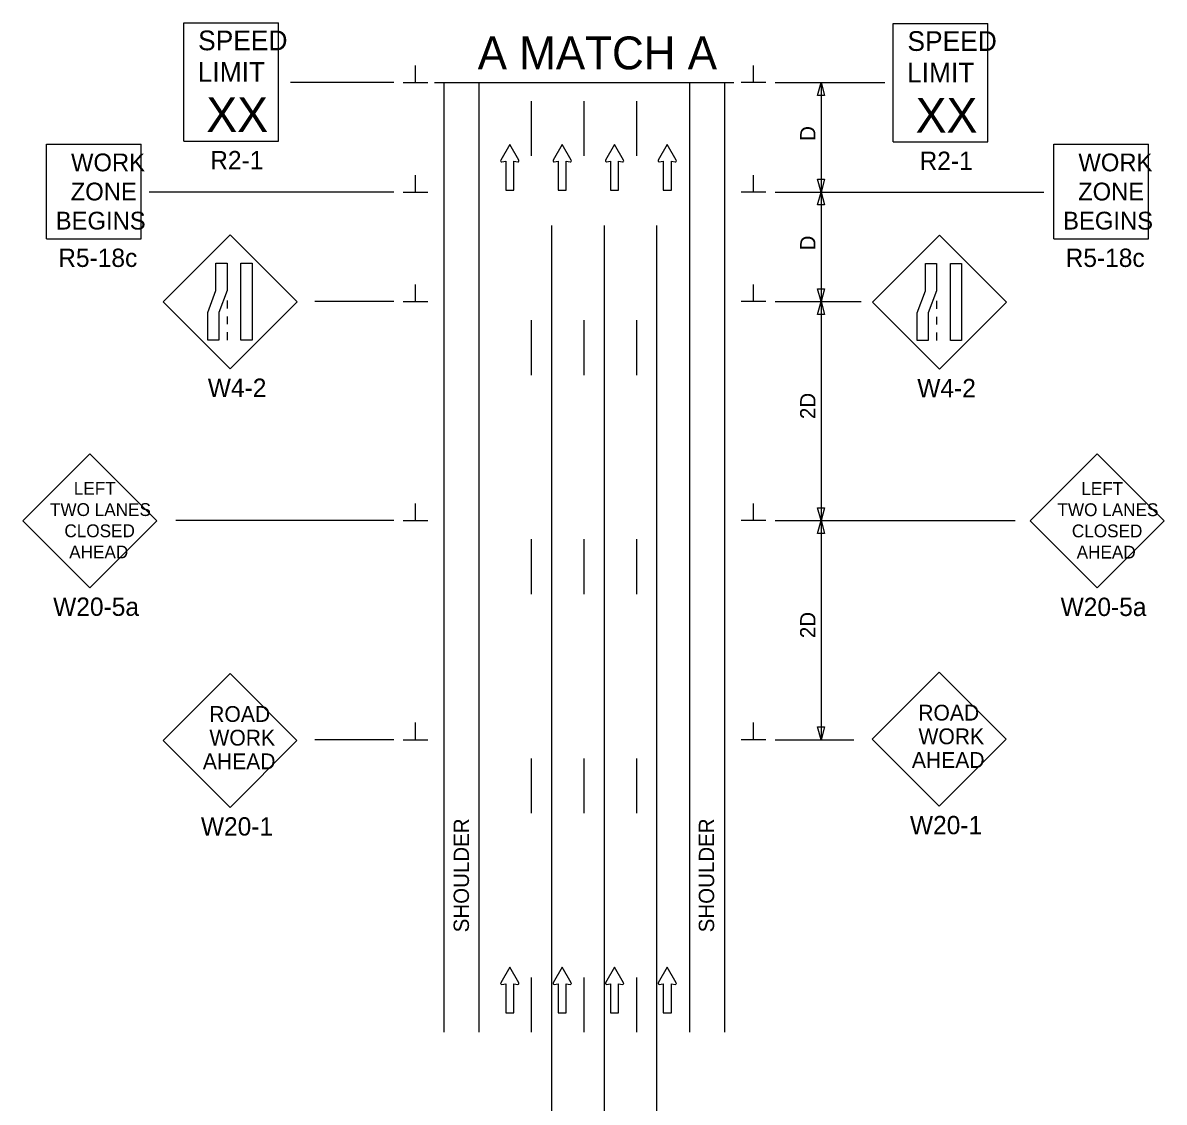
# Model space of a CAD drawing. Extents: x 16604 to 19504, y 6997 to 8305.
# Drawn here: x 17835 to 18356, y 7711 to 8204 of the extents above; entities that cross this region are included whole.
import ezdxf

# ---------------------------------------------------------------- set-up
doc = ezdxf.new("R2010")
doc.units = 0
for name, color, linetype in [('ALI_LEGAL_EX', 7, 'Continuous'), ('MT_SCRATCH_LEVEL_E', 7, 'Continuous'), ('PAVT_EDGE_EX', 7, 'Continuous'), ('TRAFFIC_SIGNS_PR', 7, 'Continuous'), ('TYPICAL_TEXT_DIMEN_PR', 7, 'Continuous')]:
    doc.layers.add(name, color=color, linetype=linetype)

msp = doc.modelspace()

# ---------------------------------------------------------------- linework, layer by layer
at = {"layer": 'ALI_LEGAL_EX'}
for p, q in [((18076.31, 7500.83), (18076.31, 8111.03)), ((18100.31, 7500.83), (18100.31, 8111.03)), ((18124.31, 7500.83), (18124.31, 8111.03))]:
    msp.add_line(p, q, dxfattribs=at)
for points in [[(18067.08, 8142.78), (18067.08, 8167.78)], [(18091.08, 8142.78), (18091.08, 8167.78)], [(18115.08, 8142.78), (18115.08, 8167.78)], [(18067.08, 8042.78), (18067.08, 8067.78)], [(18091.08, 8042.78), (18091.08, 8067.78)], [(18115.08, 8042.78), (18115.08, 8067.78)], [(18067.08, 7942.78), (18067.08, 7967.78)], [(18091.08, 7942.78), (18091.08, 7967.78)], [(18115.08, 7942.78), (18115.08, 7967.78)], [(18067.08, 7842.78), (18067.08, 7867.78)], [(18091.08, 7842.78), (18091.08, 7867.78)], [(18115.08, 7842.78), (18115.08, 7867.78)], [(18067.08, 7742.78), (18067.08, 7767.78)], [(18091.08, 7742.78), (18091.08, 7767.78)], [(18115.08, 7742.78), (18115.08, 7767.78)]]:
    msp.add_lwpolyline(points, dxfattribs=at)
at = {"layer": 'MT_SCRATCH_LEVEL_E'}
for p, q in [((18057.12, 8148.06), (18053.01, 8140.82)), ((18061.27, 8140.82), (18057.12, 8148.06)), ((18081.02, 8148.06), (18076.91, 8140.82)), ((18085.17, 8140.82), (18081.02, 8148.06)), ((18104.93, 8148.06), (18100.82, 8140.82)), ((18109.08, 8140.82), (18104.93, 8148.06)), ((18128.98, 8148.06), (18124.87, 8140.82)), ((18133.13, 8140.82), (18128.98, 8148.06)), ((18053.49, 8140.13), (18055.27, 8140.45)), ((18055.27, 8140.45), (18055.27, 8127.19)), ((18059.01, 8127.19), (18059.01, 8140.45)), ((18059.01, 8140.45), (18060.79, 8140.13)), ((18077.4, 8140.13), (18079.17, 8140.45)), ((18079.17, 8140.45), (18079.17, 8127.19)), ((18082.91, 8127.19), (18082.91, 8140.45)), ((18082.91, 8140.45), (18084.69, 8140.13)), ((18101.3, 8140.13), (18103.08, 8140.45)), ((18103.08, 8140.45), (18103.08, 8127.19)), ((18106.82, 8127.19), (18106.82, 8140.45)), ((18106.82, 8140.45), (18108.6, 8140.13)), ((18125.35, 8140.13), (18127.13, 8140.45)), ((18127.13, 8140.45), (18127.13, 8127.19)), ((18130.87, 8127.19), (18130.87, 8140.45)), ((18130.87, 8140.45), (18132.65, 8140.13)), ((18055.27, 8127.19), (18059.01, 8127.19)), ((18079.17, 8127.19), (18082.91, 8127.19)), ((18103.08, 8127.19), (18106.82, 8127.19)), ((18127.13, 8127.19), (18130.87, 8127.19)), ((18057.12, 7772.53), (18053.01, 7765.29)), ((18061.27, 7765.29), (18057.12, 7772.53)), ((18081.02, 7772.53), (18076.91, 7765.29)), ((18085.17, 7765.29), (18081.02, 7772.53)), ((18104.93, 7772.53), (18100.82, 7765.29)), ((18109.08, 7765.29), (18104.93, 7772.53)), ((18128.98, 7772.53), (18124.87, 7765.29)), ((18133.13, 7765.29), (18128.98, 7772.53)), ((18053.49, 7764.61), (18055.27, 7764.92)), ((18055.27, 7764.92), (18055.27, 7751.66)), ((18059.01, 7751.66), (18059.01, 7764.92)), ((18059.01, 7764.92), (18060.79, 7764.61)), ((18077.4, 7764.61), (18079.17, 7764.92)), ((18079.17, 7764.92), (18079.17, 7751.66)), ((18082.91, 7751.66), (18082.91, 7764.92)), ((18082.91, 7764.92), (18084.69, 7764.61)), ((18101.3, 7764.61), (18103.08, 7764.92)), ((18103.08, 7764.92), (18103.08, 7751.66)), ((18106.82, 7751.66), (18106.82, 7764.92)), ((18106.82, 7764.92), (18108.6, 7764.61)), ((18125.35, 7764.61), (18127.13, 7764.92)), ((18127.13, 7764.92), (18127.13, 7751.66)), ((18130.87, 7751.66), (18130.87, 7764.92)), ((18130.87, 7764.92), (18132.65, 7764.61)), ((18055.27, 7751.66), (18059.01, 7751.66)), ((18079.17, 7751.66), (18082.91, 7751.66)), ((18103.08, 7751.66), (18106.82, 7751.66)), ((18127.13, 7751.66), (18130.87, 7751.66))]:
    msp.add_line(p, q, dxfattribs=at)
for centre, start, end in [((18053.42, 8140.59), 150.4248, 279.9638), ((18060.86, 8140.59), 260.0362, 29.7731), ((18077.32, 8140.59), 150.4248, 279.9638), ((18084.76, 8140.59), 260.0362, 29.7731), ((18101.22, 8140.59), 150.4248, 279.9638), ((18108.67, 8140.59), 260.0362, 29.7731), ((18125.28, 8140.59), 150.4248, 279.9638), ((18132.72, 8140.59), 260.0362, 29.7731), ((18053.42, 7765.06), 150.4248, 279.9638), ((18060.86, 7765.07), 260.0362, 29.7731), ((18077.32, 7765.06), 150.4248, 279.9638), ((18084.76, 7765.07), 260.0362, 29.7731), ((18101.22, 7765.06), 150.4248, 279.9638), ((18108.67, 7765.07), 260.0362, 29.7731), ((18125.28, 7765.06), 150.4248, 279.9638), ((18132.72, 7765.07), 260.0362, 29.7731)]:
    msp.add_arc(centre, 0.463, start, end, dxfattribs=at)
at = {"layer": 'PAVT_EDGE_EX'}
for p, q in [((18027.08, 8176.3), (18027.08, 7742.78)), ((18043.08, 8176.3), (18043.08, 7742.78)), ((18139.08, 8176.3), (18139.08, 7742.78)), ((18155.08, 8176.3), (18155.08, 7742.78))]:
    msp.add_line(p, q, dxfattribs=at)
at = {"layer": 'TRAFFIC_SIGNS_PR'}
for p, q in [((17908.41, 8203.55), (17951.61, 8203.55)), ((17908.41, 8149.55), (17908.41, 8203.55)), ((17951.61, 8149.55), (17951.61, 8203.55)), ((18232.11, 8203.26), (18275.31, 8203.26)), ((18232.11, 8149.26), (18232.11, 8203.26)), ((18275.31, 8149.26), (18275.31, 8203.26)), ((17845.66, 8104.98), (17845.66, 8148.18)), ((17845.66, 8148.18), (17888.86, 8148.18)), ((17888.86, 8104.98), (17888.86, 8148.18)), ((17908.41, 8149.55), (17951.61, 8149.55)), ((18232.11, 8149.26), (18275.31, 8149.26)), ((18305.36, 8104.98), (18305.36, 8148.18)), ((18305.36, 8148.18), (18348.56, 8148.18)), ((18348.56, 8104.98), (18348.56, 8148.18)), ((17845.66, 8104.98), (17888.86, 8104.98)), ((17929.51, 8106.75), (17898.96, 8076.2)), ((17960.05, 8076.2), (17929.51, 8106.75)), ((18253.26, 8106.59), (18222.71, 8076.04)), ((18283.8, 8076.04), (18253.26, 8106.59)), ((18305.36, 8104.98), (18348.56, 8104.98)), ((17898.96, 8076.2), (17929.51, 8045.65)), ((17928.1, 8076.75), (17928.1, 8073.15)), ((17929.51, 8045.65), (17960.05, 8076.2)), ((18222.71, 8076.04), (18253.26, 8045.5)), ((18251.85, 8076.6), (18251.85, 8073)), ((18253.26, 8045.5), (18283.8, 8076.04)), ((17928.1, 8069.55), (17928.1, 8065.95)), ((18251.85, 8069.4), (18251.85, 8065.8)), ((17928.1, 8062.35), (17928.1, 8058.75)), ((18251.85, 8062.2), (18251.85, 8058.6)), ((17865.47, 8006.78), (17834.92, 7976.24)), ((17896.01, 7976.24), (17865.47, 8006.78)), ((18325.21, 8006.72), (18294.66, 7976.18)), ((18355.75, 7976.18), (18325.21, 8006.72)), ((17834.92, 7976.24), (17865.47, 7945.69)), ((17865.47, 7945.69), (17896.01, 7976.24)), ((18294.66, 7976.18), (18325.21, 7945.63)), ((18325.21, 7945.63), (18355.75, 7976.18)), ((17929.48, 7906.5), (17898.93, 7875.95)), ((17960.02, 7875.95), (17929.48, 7906.5)), ((18253.03, 7907.11), (18222.49, 7876.56)), ((18283.58, 7876.56), (18253.03, 7907.11)), ((17898.93, 7875.95), (17929.48, 7845.41)), ((17929.48, 7845.41), (17960.02, 7875.95)), ((18222.49, 7876.56), (18253.03, 7846.01)), ((18253.03, 7846.01), (18283.58, 7876.56))]:
    msp.add_line(p, q, dxfattribs=at)
for points in [[(17928.1, 8093.9), (17928.1, 8081.32), (17924.34, 8071.33), (17924.34, 8058.75), (17919.29, 8058.75), (17919.29, 8071.33), (17923.05, 8081.32), (17923.05, 8093.9)], [(17939.51, 8093.9), (17939.51, 8058.75), (17934.45, 8058.75), (17934.45, 8093.9)], [(18251.85, 8093.75), (18251.85, 8081.17), (18248.09, 8071.18), (18248.09, 8058.6), (18243.04, 8058.6), (18243.04, 8071.18), (18246.8, 8081.17), (18246.8, 8093.75)], [(18263.26, 8093.75), (18263.26, 8058.6), (18258.2, 8058.6), (18258.2, 8093.75)]]:
    msp.add_lwpolyline(points, close=True, dxfattribs=at)
at = {"layer": 'TYPICAL_TEXT_DIMEN_PR'}
for p, q in [((18014.05, 8176.3), (18014.05, 8184.08)), ((18168.3, 8176.3), (18168.3, 8184.08)), ((18004.18, 8176.3), (17957, 8176.3)), ((18008.43, 8176.3), (18019.68, 8176.3)), ((18022.75, 8176.3), (18159.4, 8176.3)), ((18173.93, 8176.3), (18162.68, 8176.3)), ((18178.18, 8176.3), (18228.33, 8176.3)), ((18197.61, 8170.44), (18199.18, 8176.3)), ((18199.18, 8176.3), (18200.75, 8170.44)), ((18199.18, 8176.3), (18199.18, 8126.3)), ((18199.18, 8170.44), (18197.61, 8170.44)), ((18200.75, 8170.44), (18199.18, 8170.44)), ((18014.05, 8126.3), (18014.05, 8134.08)), ((18168.3, 8126.3), (18168.3, 8134.08)), ((18199.18, 8126.3), (18197.6, 8132.16)), ((18197.6, 8132.16), (18199.18, 8132.16)), ((18199.18, 8132.16), (18200.75, 8132.16)), ((18200.75, 8132.16), (18199.18, 8126.3)), ((18004.18, 8126.3), (17892.61, 8126.3)), ((18008.43, 8126.3), (18019.68, 8126.3)), ((18173.93, 8126.3), (18162.68, 8126.3)), ((18178.18, 8126.3), (18300.79, 8126.3)), ((18197.61, 8120.44), (18199.18, 8126.3)), ((18199.18, 8126.3), (18200.75, 8120.44)), ((18199.18, 8126.3), (18199.18, 8076.3)), ((18199.18, 8120.44), (18197.61, 8120.44)), ((18200.75, 8120.44), (18199.18, 8120.44)), ((18014.05, 8076.3), (18014.05, 8084.08)), ((18168.3, 8076.3), (18168.3, 8084.08)), ((18199.18, 8076.3), (18197.6, 8082.16)), ((18197.6, 8082.16), (18199.18, 8082.16)), ((18199.18, 8082.16), (18200.75, 8082.16)), ((18200.75, 8082.16), (18199.18, 8076.3)), ((18004.18, 8076.3), (17968.18, 8076.3)), ((18008.43, 8076.3), (18019.68, 8076.3)), ((18173.93, 8076.3), (18162.68, 8076.3)), ((18178.18, 8076.3), (18217.52, 8076.3)), ((18197.61, 8070.44), (18199.18, 8076.3)), ((18199.18, 8076.3), (18199.18, 7976.3)), ((18199.18, 8076.3), (18200.75, 8070.44)), ((18199.18, 8070.44), (18197.61, 8070.44)), ((18200.75, 8070.44), (18199.18, 8070.44)), ((18014.05, 7976.3), (18014.05, 7984.08)), ((18168.3, 7976.3), (18168.3, 7984.08)), ((18199.18, 7976.3), (18197.61, 7982.16)), ((18197.61, 7982.16), (18199.18, 7982.16)), ((18199.18, 7982.16), (18200.75, 7982.16)), ((18200.75, 7982.16), (18199.18, 7976.3)), ((18004.18, 7976.3), (17904.81, 7976.3)), ((18008.43, 7976.3), (18019.68, 7976.3)), ((18173.93, 7976.3), (18162.68, 7976.3)), ((18178.18, 7976.3), (18287.81, 7976.3)), ((18197.61, 7970.44), (18199.18, 7976.3)), ((18199.18, 7976.3), (18199.18, 7876.3)), ((18199.18, 7976.3), (18200.75, 7970.44)), ((18199.18, 7970.44), (18197.61, 7970.44)), ((18200.75, 7970.44), (18199.18, 7970.44)), ((18014.05, 7876.3), (18014.05, 7884.08)), ((18168.3, 7876.3), (18168.3, 7884.08)), ((18199.18, 7876.3), (18197.61, 7882.16)), ((18197.61, 7882.16), (18199.18, 7882.16)), ((18199.18, 7882.16), (18200.75, 7882.16)), ((18200.75, 7882.16), (18199.18, 7876.3)), ((18004.18, 7876.3), (17968.18, 7876.3)), ((18008.43, 7876.3), (18019.68, 7876.3)), ((18173.93, 7876.3), (18162.68, 7876.3)), ((18178.18, 7876.3), (18214.18, 7876.3))]:
    msp.add_line(p, q, dxfattribs=at)

# ---------------------------------------------------------------- texts
at = {"layer": 'TRAFFIC_SIGNS_PR'}
for s, height, p in [('SPEED', 9, (17914.9, 8191.02)), ('SPEED', 9, (18238.59, 8190.73)), ('LIMIT', 9, (17914.72, 8176.62)), ('LIMIT', 9, (18238.41, 8176.33)), ('XX', 15.785, (17918.67, 8153.78)), ('XX', 15.785, (18242.36, 8153.48)), ('WORK', 8.119, (17856.91, 8135.77)), ('R2-1', 8.37, (17920.43, 8136.68)), ('R2-1', 8.37, (18244.12, 8136.39)), ('WORK', 8.119, (18316.61, 8135.77)), ('ZONE', 8.119, (17856.77, 8122.48)), ('ZONE', 8.119, (18316.47, 8122.48)), ('BEGINS', 8.119, (17849.94, 8109.19)), ('BEGINS', 8.119, (18309.64, 8109.19)), ('R5-18c', 8.37, (17851.07, 8092.11)), ('R5-18c', 8.37, (18310.77, 8092.11)), ('W4-2', 8.37, (17919.33, 8032.78)), ('W4-2', 8.37, (18243.09, 8032.63)), ('LEFT', 5.85, (17858.19, 7988.09)), ('LEFT', 5.85, (18317.93, 7988.03)), ('TWO LANES', 5.85, (17847.31, 7978.41)), ('TWO LANES', 5.85, (18307.05, 7978.35)), ('CLOSED', 5.85, (17853.89, 7968.74)), ('CLOSED', 5.85, (18313.63, 7968.68)), ('AHEAD', 5.85, (17856.08, 7959.06)), ('AHEAD', 5.85, (18315.82, 7959)), ('W20-5a', 8.37, (17848.75, 7932.82)), ('W20-5a', 8.37, (18308.49, 7932.76)), ('ROAD', 7.2, (17919.96, 7884.43)), ('ROAD', 7.2, (18243.52, 7885.04)), ('WORK', 7.2, (17920.08, 7873.63)), ('WORK', 7.2, (18243.64, 7874.24)), ('AHEAD', 7.2, (17917.06, 7862.83)), ('AHEAD', 7.2, (18240.62, 7863.44)), ('W20-1', 8.37, (17916.17, 7832.54)), ('W20-1', 8.37, (18239.73, 7833.14))]:
    msp.add_text(s, height=height, dxfattribs=at).set_placement(p)
at = {"layer": 'TYPICAL_TEXT_DIMEN_PR'}
msp.add_text('A MATCH A', height=15, dxfattribs=at).set_placement((18042.49, 8182.31))
for s, p in [('D', (18196.62, 8149.66)), ('D', (18196.62, 8099.66)), ('2D', (18196.62, 8022.66)), ('2D', (18196.62, 7922.66)), ('SHOULDER', (18038.51, 7788.36)), ('SHOULDER', (18150.38, 7788.36))]:
    msp.add_text(s, height=7, rotation=90, dxfattribs=at).set_placement(p)

doc.saveas('drawing.dxf')
